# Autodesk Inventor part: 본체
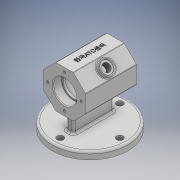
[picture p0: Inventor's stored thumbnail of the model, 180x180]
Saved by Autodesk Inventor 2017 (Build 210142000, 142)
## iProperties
Part Number: 본체
Material: 일반
Document SubType Name: Modeling
Designer: mrc
Density: 1 g/cm^3
Appearance: 기본값
Mass: 205.854 g
Surface Area: 511.831 cm^2
Volume: 205.854 cm^3
Author: mrc
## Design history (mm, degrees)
sketch "스케치1" dims "d0" = 58
  geometry: L1 (12.012, 29)-(29, 12.012); L2 (29, 12.012)-(29, -12.012); L3 (29, -12.012)-(12.012, -29); L4 (12.012, -29)-(-12.012, -29); L5 (-12.012, -29)-(-29, -12.012); L6 (-29, -12.012)-(-29, 12.012); L7 (-29, 12.012)-(-12.012, 29); L8 (-12.012, 29)-(12.012, 29); 4 further points
  constraints: 16 end point, 2 coincident, 1 midpoint, 1 vertical alignment, 19 other
extrude "돌출1" new body sketch "스케치1" stored distance "d1" = 70; taper "d2" = 0 deg
node "작업 평면1"
sketch "스케치3"
  geometry: C1 r 52 at (0, 0); 1 further point
  constraints: 1 centre point, 1 coincident
  dimensions: "d4" = 104 diameter of C1
extrude "돌출2" join sketch "스케치3" distance "d5" = 10; taper "d6" = 0 deg
sketch "스케치4"
  geometry: L1 (-28, 0)-(28, 0); L2 (28, 0)-(28, -52); L3 (28, -52)-(-28, -52); L4 (-28, -52)-(-28, 0); L5 (52, -52)-(-52, -52) reference; 3 further points
  constraints: 8 end point, 4 midpoint, 2 parallel, 1 coincident, 1 horizontal, 1 perpendicular
  dimensions: "d7" = 56 distance of L2.end L3.end
extrude "돌출3" join sketch "스케치4" stored distance "d10" = 10; taper "d11" = 0 deg
sketch "스케치5"
  geometry: C1 r 14 at (0, 0); 1 further point
  constraints: 1 centre point, 1 coincident
  dimensions: "d12" = 28 diameter of C1
extrude "돌출4" cut sketch "스케치5" distance "d13" = 95.25; taper "d14" = 0 deg
sketch "스케치7"
  geometry: C1 r 16 at (0, 0); 1 further point
  constraints: 1 centre point, 1 coincident
  dimensions: "d15" = 32 diameter of C1
extrude "돌출5" cut sketch "스케치7" distance "d16" = 12; taper "d17" = 0 deg
sketch "스케치8"
  geometry: C1 r 22 at (0, 0); 1 further point
  constraints: 1 centre point, 1 coincident
  dimensions: "d18" = 44 diameter of C1
extrude "돌출6" cut sketch "스케치8" stored distance "d19" = 40; taper "d20" = 0 deg
sketch "스케치9"
  geometry: 2 further points
  constraints: 1 vertical alignment
  dimensions: "d21" = 23 distance of point (0, 0) point (0, 23)
hole "구멍1" sketch "스케치9" at (0, 23) diameter "d22" = 3.459; stored, may be unused: countersink angle "d26" = 90 deg, drill point angle "d28" = 118 deg; dims "d23" = 8, "d24" = 4, "d25" = 2, "d27" = 10
sketch "스케치10"
  geometry: C1 r 4.5 at (0, 41); 1 further point
  constraints: 1 centre point, 1 vertical alignment
  dimensions: "d32" = 9 diameter of C1; "d33" = 41 distance of point (0, 0) C1.centre
extrude "돌출7" cut sketch "스케치10" distance "d34" = 47; taper "d35" = 0 deg
sketch "스케치11"
  geometry: C1 r 10 at (-12.012, 35); 1 further point
  constraints: 1 centre point, 1 coincident
  dimensions: "d39" = 20 diameter of C1
extrude "돌출8" join sketch "스케치11" distance "d40" = 5; taper "d41" = 0 deg
sketch "스케치12"
  geometry: C1 r 8 at (0, 0); 1 further point
  constraints: 1 centre point, 1 coincident
  dimensions: "d42" = 16 diameter of C1
extrude "돌출9" cut sketch "스케치12" distance "d43" = 2; taper "d44" = 0 deg
hole "구멍2" diameter "d47" = 10.917; stored, may be unused: countersink angle "d51" = 90 deg, drill point angle "d53" = 118 deg; dims "d45" = 10, "d46" = 10, "d48" = 24, "d49" = 4, "d50" = 2, "d52" = 29.1
sketch "스케치14"
  geometry: L1 (6.005, -56.054)-(6.005, -14.575); L2 (6.005, -14.575)-(18.02, -14.575); L3 (18.02, -14.575)-(18.02, -56.054); L4 (18.02, -56.054)-(6.005, -56.054); L5 (12.012, -14.575)-(12.012, -56.054); L6 (12.012, -35)-(6.005, -35); L7 (-16.988, 0)-(-16.988, -70) reference
  constraints: 4 end point, 2 midpoint, 1 perpendicular, 1 point on line, 2 other
  dimensions: "d58" = 29 distance between parallel lines of L7 L5
extrude "돌출10" join sketch "스케치14" distance "d59" = 0.5; taper "d60" = 0 deg
fillet "모깎기1" dims "d61" = 3
chamfer "모따기1" distance "d62" = 1; stored, may be unused: second distance "d63" = 2, angle "d64" = 45 deg
fillet "모깎기2" dims "d65" = 1
fillet "모깎기3" dims "d66" = 1
fillet "모깎기5" dims "d68" = 0.3
sketch "스케치15"
  geometry: 1 further point
fillet "모깎기6" dims "d69" = 3
fillet "모깎기7" dims "d70" = 3
node "솔리드1"
mirror "미러1"
pattern_circular "원형 패턴1" dims angle "d30" = 360 deg
mirror "미러2"
pattern_circular "원형 패턴2" dims angle "d37" = 360 deg
other parameters: "d3" = -62
